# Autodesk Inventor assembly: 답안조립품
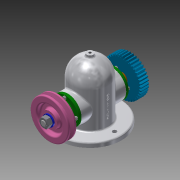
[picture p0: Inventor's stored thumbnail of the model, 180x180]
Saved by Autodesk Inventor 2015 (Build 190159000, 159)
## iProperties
Created: 2019-11
Part Number: 답안조립품
Document SubType Name: Assembly
Designer: 101020202
Author: 101020202
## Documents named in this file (14)
- C:\Users\101020202\Desktop\491104V1035\답안조립품.iam
- C:\Users\101020202\Desktop\491104V1035\V-벨트풀리.ipt
- V-벨트풀리.ipt
- C:\Users\101020202\Desktop\491104V1035\너트 M12x1.25.ipt
- C:\Users\101020202\Desktop\491104V1035\베어링 6203.ipt
- C:\Users\101020202\Desktop\491104V1035\본체.ipt
- C:\Users\101020202\Desktop\491104V1035\볼트 M4.ipt
- C:\Users\101020202\Desktop\491104V1035\부시.ipt
- C:\Users\101020202\Desktop\491104V1035\스퍼기어.ipt
- C:\Users\101020202\Desktop\491104V1035\오일 실 26 38 8.ipt
- C:\Users\101020202\Desktop\491104V1035\와셔 12x24.ipt
- C:\Users\101020202\Desktop\491104V1035\축.ipt
- C:\Users\101020202\Desktop\491104V1035\커버.ipt
- C:\Users\101020202\Desktop\491104V1035\키 5x5x12.ipt
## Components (1 placed, 1 different names)
1. V-벨트풀리:1 — 각도:3
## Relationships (1: Angle 1)
- 각도:3 [Angle]: V-벨트풀리:1
